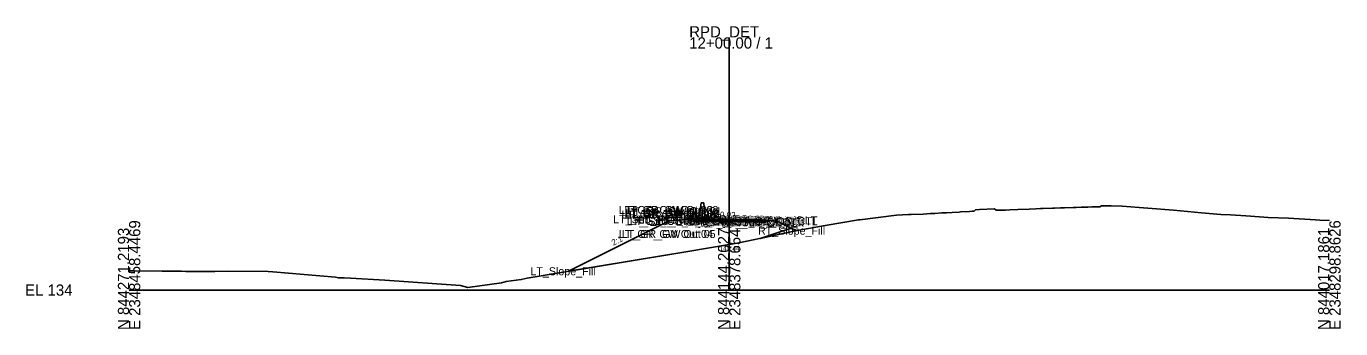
# Model space of a CAD drawing. Extents: x -26 to 2348503, y -10 to 844218.
# Drawn here: x -25.7 to 302.8, y 1990.3 to 2066.1 of the extents above; entities that cross this region are included whole.
import ezdxf

# ---------------------------------------------------------------- set-up
doc = ezdxf.new("R2010")
doc.units = 0
for name, color, linetype in [('Default', 7, 'Continuous'), ('Exist Cross Section Cell', 7, 'Continuous'), ('Exist XS Center Line Elevation Label', 7, 'Continuous'), ('Exist XS Ground Line', 7, 'Continuous'), ('Old_Level_1', 7, 'Continuous'), ('Prop CMT Pvmt Course 1', 7, 'Continuous'), ('Prop CMT Pvmt Course 2', 7, 'Continuous'), ('Prop CMT Pvmt Course 3', 7, 'Continuous'), ('Prop CMT Pvmt Surface', 7, 'Continuous'), ('Prop CMT Pvmt Surface Shoulder', 7, 'Continuous'), ('Prop CMT Shld Paved Course 1', 7, 'Continuous'), ('Prop CMT Shld Paved Course 2', 7, 'Continuous'), ('Prop CMT Shld Paved Course 3', 7, 'Continuous'), ('Prop CMT Slope Grass', 7, 'Continuous'), ('Prop CMT Subgrade Earthwork', 7, 'Continuous'), ('Prop XS Earthwork Shape', 7, 'Continuous'), ('Prop XS SE Text', 7, 'Continuous'), ('Scratch_Level_6', 7, 'Continuous'), ('Typical Median Barrier CELL', 7, 'Continuous')]:
    doc.layers.add(name, color=color, linetype=linetype)

# ---------------------------------------------------------------- blocks, each defined once
blk = doc.blocks.new('TYPE T DOUBLE FACE BARRIER')
at = {"layer": 'Typical Median Barrier CELL'}
for p, q in [((-0.33, 3.83), (-0.6, 1.3)), ((0, 3.83), (-0.33, 3.83)), ((0, 3.83), (0.33, 3.83)), ((0.33, 3.83), (0.6, 1.3)), ((-0.75, 0.91), (-1.21, 0.25)), ((-1.21, -0.17), (-1.21, 0.25)), ((0, 0), (0, 0)), ((0.75, 0.91), (1.21, 0.25)), ((1.21, -0.17), (1.21, 0.25)), ((-1.21, -0.17), (1.21, -0.17))]:
    blk.add_line(p, q, dxfattribs=at)
for centre, start, end in [((-1.43, 1.38), 325.0039, 353.9447), ((1.43, 1.38), 186.0553, 214.9937)]:
    blk.add_arc(centre, 0.833, start, end, dxfattribs=at)

msp = doc.modelspace()

# ---------------------------------------------------------------- linework, layer by layer
at = {"layer": 'Exist Cross Section Cell'}
for p, q in [((150, 2000), (150, 2063.28)), ((0, 2000), (150, 2000)), ((150, 2000), (300, 2000))]:
    msp.add_line(p, q, dxfattribs=at)
at = {"layer": 'Exist XS Ground Line'}
msp.add_lwpolyline([(0, 2004.81), (1.26, 2004.8), (8.23, 2004.75), (13.07, 2004.7), (14.18, 2004.69), (15.94, 2004.69), (21.43, 2004.68), (24.88, 2004.7), (34.74, 2004.63), (35.94, 2004.6), (51.57, 2003.2), (52.36, 2003.1), (53.72, 2003.04), (55.31, 2002.95), (63.93, 2002.5), (82.84, 2001.17), (84.64, 2000.68), (93.09, 2001.81), (94.25, 2002.13), (98.02, 2002.64), (99.49, 2003.01), (139.62, 2009.63), (150, 2011.44), (151.99, 2011.78), (154.79, 2012.29), (166.59, 2014.85), (173.96, 2016.13), (182.3, 2017.57), (182.66, 2017.61), (191.82, 2018.73), (193.28, 2018.8), (194.8, 2018.89), (195.48, 2018.91), (198.45, 2019.04), (200.27, 2019.14), (201.4, 2019.21), (203.14, 2019.31), (203.89, 2019.35), (204.35, 2019.37), (205.69, 2019.44), (207.5, 2019.54), (207.82, 2019.56), (210.06, 2019.68), (210.8, 2019.72), (211.2, 2019.72), (211.59, 2020.12), (212.58, 2020.17), (216.27, 2020.31), (216.7, 2019.97), (217.11, 2019.99), (217.57, 2020), (219.09, 2020.05), (220.17, 2020.1), (222.16, 2020.18), (224.97, 2020.3), (226.65, 2020.36), (227.8, 2020.39), (228.45, 2020.41), (230.83, 2020.5), (231.3, 2020.52), (232.83, 2020.58), (233.8, 2020.61), (236, 2020.69), (236.75, 2020.71), (237.97, 2020.75), (239.67, 2020.8), (240.67, 2020.83), (242.66, 2020.85), (243.09, 2021.09), (245.44, 2021.09), (248.18, 2021.01), (261.08, 2019.99), (268.04, 2019.36), (272.89, 2018.96), (275.29, 2018.81), (279.13, 2018.55), (282.55, 2018.32), (284.7, 2018.19), (289.8, 2018.01), (296.51, 2017.58), (297.64, 2017.5), (300, 2017.41)], dxfattribs=at)
at = {"layer": 'Prop CMT Pvmt Course 1'}
for p, q in [((150, 2017.71), (142, 2017.87)), ((142, 2017.87), (142, 2017.62)), ((142, 2017.62), (150, 2017.46)), ((150, 2017.46), (150, 2017.71)), ((150, 2017.71), (158, 2017.55)), ((150, 2017.46), (150, 2017.71)), ((150, 2017.46), (150, 2017.59)), ((150, 2017.59), (150, 2017.59)), ((150, 2017.59), (150, 2017.46)), ((150, 2017.46), (150, 2017.59)), ((150, 2017.59), (150, 2017.59)), ((150, 2017.59), (150, 2017.46)), ((150, 2017.46), (150, 2017.46)), ((158, 2017.3), (150, 2017.46)), ((150, 2017.46), (150, 2017.46)), ((158, 2017.55), (158, 2017.3))]:
    msp.add_line(p, q, dxfattribs=at)
at = {"layer": 'Prop CMT Pvmt Course 2'}
for p, q in [((142, 2017.62), (150, 2017.46)), ((150, 2017.46), (142, 2017.62)), ((142, 2017.62), (142, 2017.62)), ((150, 2017.46), (150, 2017.46)), ((158, 2017.3), (150, 2017.46)), ((150, 2017.46), (150, 2017.46)), ((150, 2017.46), (158, 2017.3)), ((158, 2017.3), (158, 2017.3))]:
    msp.add_line(p, q, dxfattribs=at)
at = {"layer": 'Prop CMT Pvmt Course 3'}
for p, q in [((150, 2017.46), (142, 2017.62)), ((142, 2017.62), (142, 2017.29)), ((142, 2017.29), (150, 2017.13)), ((150, 2017.13), (150, 2017.46)), ((150, 2017.46), (158, 2017.3)), ((150, 2017.13), (150, 2017.46)), ((158, 2017.3), (158, 2016.97)), ((158, 2016.97), (150, 2017.13))]:
    msp.add_line(p, q, dxfattribs=at)
at = {"layer": 'Prop CMT Pvmt Surface'}
for q in [(142, 2017.87), (158, 2017.55)]:
    msp.add_line((150, 2017.71), q, dxfattribs=at)
at = {"layer": 'Prop CMT Pvmt Surface Shoulder'}
for p, q in [((142, 2017.87), (142, 2017.87)), ((158, 2017.55), (158, 2017.55))]:
    msp.add_line(p, q, dxfattribs=at)
at = {"layer": 'Prop CMT Shld Paved Course 1'}
for p, q in [((142, 2017.87), (141.74, 2017.62)), ((141.74, 2017.62), (142, 2017.62)), ((142, 2017.87), (142, 2017.87)), ((142, 2017.62), (142, 2017.87)), ((158, 2017.55), (158, 2017.55)), ((158, 2017.55), (158.26, 2017.3)), ((158, 2017.3), (158, 2017.55)), ((158.26, 2017.3), (158, 2017.3))]:
    msp.add_line(p, q, dxfattribs=at)
at = {"layer": 'Prop CMT Shld Paved Course 2'}
for p, q in [((142, 2017.62), (141.74, 2017.62)), ((141.74, 2017.62), (141.74, 2017.62)), ((141.74, 2017.62), (142, 2017.62)), ((142, 2017.62), (142, 2017.62)), ((158, 2017.3), (158.26, 2017.3)), ((158.26, 2017.3), (158, 2017.3)), ((158, 2017.3), (158, 2017.3)), ((158.26, 2017.3), (158.26, 2017.3))]:
    msp.add_line(p, q, dxfattribs=at)
at = {"layer": 'Prop CMT Shld Paved Course 3'}
for p, q in [((141.24, 2017.61), (140.9, 2017.27)), ((140.9, 2017.27), (142, 2017.29)), ((141.74, 2017.62), (141.24, 2017.61)), ((142, 2017.62), (141.74, 2017.62)), ((142, 2017.29), (142, 2017.62)), ((158, 2017.3), (158.26, 2017.3)), ((158, 2016.97), (158, 2017.3)), ((158.26, 2017.3), (158.76, 2017.29)), ((158.76, 2017.29), (159.1, 2016.95)), ((159.1, 2016.95), (158, 2016.97))]:
    msp.add_line(p, q, dxfattribs=at)
at = {"layer": 'Prop CMT Slope Grass'}
for p, q in [((135, 2017.31), (109.79, 2004.71)), ((142, 2017.87), (135, 2017.31)), ((158, 2017.55), (162, 2017.23)), ((162, 2017.23), (166.72, 2014.87))]:
    msp.add_line(p, q, dxfattribs=at)
at = {"layer": 'Prop CMT Subgrade Earthwork'}
for p, q in [((140.9, 2017.27), (140.43, 2017.75)), ((142, 2017.29), (140.9, 2017.27)), ((150, 2017.13), (142, 2017.29)), ((159.1, 2016.95), (159.57, 2017.43)), ((150, 2017.13), (158, 2016.97)), ((158, 2016.97), (159.1, 2016.95))]:
    msp.add_line(p, q, dxfattribs=at)
at = {"layer": 'Prop XS Earthwork Shape'}
msp.add_lwpolyline([(162, 2017.23), (166.72, 2014.87), (166.59, 2014.85), (154.79, 2012.29), (151.99, 2011.78), (150, 2011.44), (139.62, 2009.63), (109.79, 2004.71), (135, 2017.31), (140.43, 2017.75), (140.9, 2017.27), (142, 2017.29), (150, 2017.13), (158, 2016.97), (159.1, 2016.95), (159.57, 2017.43)], close=True, dxfattribs=at)
at = {"layer": 'Scratch_Level_6'}
for p, q in [((165.45, 2015.51), (159.27, 2013.44)), ((166.66, 2014.9), (165.45, 2015.51)), ((166.72, 2014.87), (166.66, 2014.9)), ((159.27, 2013.44), (157.7, 2012.92))]:
    msp.add_line(p, q, dxfattribs=at)
msp.add_lwpolyline([(157.7, 2012.92), (166.59, 2014.85), (166.72, 2014.87)], dxfattribs=at)

# ---------------------------------------------------------------- block references
at = {"layer": 'Old_Level_1', "yscale": -0.9999999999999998, "rotation": 178.71900092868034}
msp.add_blockref('TYPE T DOUBLE FACE BARRIER', (143.21, 2018.01), dxfattribs=at)

# ---------------------------------------------------------------- texts
at = {"layer": 'Default'}
for s, height, p in [('LT_GR_GW Out 03', 2, (122.44, 2019.05)), ('LT_GR_GW Out 02', 2, (123.78, 2019.05)), ('LT_GR_GW Out 09', 2, (123.78, 2018.47)), ('LT_GR_GW Out 01', 2, (124.61, 2018.76)), ('LT_Sub_Trench_Out_DLT', 2, (120.99, 2016.75)), ('LT_GR_GW Out 06', 2, (123.06, 2017.89)), ('LT_GR_GW Out 07', 2, (123.78, 2017.89)), ('LT_GR_GW Out 08', 2, (124.05, 2018.18)), ('LT_GS_OS_CTL', 2, (124.37, 2016.31)), ('LT_Sub_Trench_Out', 2, (125.11, 2016.27)), ('LT_PS3_Shelf_Out', 2, (127.23, 2016.61)), ('LT_PS3_OEOP', 2, (131.98, 2016.62)), ('LT_PS2_OEOP', 2, (131.98, 2016.62)), ('LT_Sub_OEOT', 2, (132.08, 2016.29)), ('LT_PV3_OEOT', 2, (132.17, 2016.62)), ('LT_PV2_OEOT', 2, (132.17, 2016.62)), ('LT_PV1_OEOT', 2, (132.74, 2016.87)), ('LT_PS1_OEOP', 2, (132.8, 2016.87)), ('RT_Sub_OEEOP', 2, (139.17, 2016.13)), ('LT_Sub_OEEOP', 2, (139.21, 2016.13)), ('RT_PV2_OEEOP', 2, (139.26, 2016.46)), ('RT_PV3_OEEOP', 2, (139.26, 2016.46)), ('LT_PV2_OEEOP', 2, (139.31, 2016.46)), ('LT_PV3_OEEOP', 2, (139.31, 2016.46)), ('RT_PV1_OEEOP', 2, (139.83, 2016.59)), ('LT_PV1_OEEOP', 2, (139.87, 2016.59)), ('RT_PV2_IEEOP', 2, (139.91, 2016.46)), ('LT_PV2_IEEOP', 2, (139.95, 2016.46)), ('RT_Sub_Trench_Out_DLT', 2, (140.09, 2016.43)), ('RT_PV1_IEEOP', 2, (140.47, 2016.59)), ('LT_PV1_IEEOP', 2, (140.52, 2016.59)), ('RT_Sub_Trench_Out', 2, (143.25, 2015.95)), ('PV2_PGL', 2, (143.91, 2016.46)), ('PV1_PGL', 2, (144.47, 2016.71)), ('RT_PS3_Shelf_Out', 2, (144.69, 2016.29)), ('RT_Sub_OEOT', 2, (148.03, 2015.97)), ('RT_PV3_OEOT', 2, (148.13, 2016.3)), ('RT_PV2_OEOT', 2, (148.13, 2016.3)), ('RT_PS3_OEOP', 2, (148.44, 2016.3)), ('RT_PS2_OEOP', 2, (148.44, 2016.3)), ('RT_PV1_OEOT', 2, (148.69, 2016.55)), ('RT_PS1_OEOP', 2, (148.76, 2016.55)), ('RT_GS_OS_CTL', 2, (151.32, 2016.23)), ('LT_GR_GW Out 04', 2, (122.44, 2013.05)), ('LT_GR_GW Out 05', 2, (123.11, 2013.05)), ('RT_Slope_Fill', 2, (157.19, 2013.87)), ('LT_Slope_Fill', 2, (100.31, 2003.71)), ('-', 0.0001, (0, 2000))]:
    msp.add_text(s, height=height, dxfattribs=at).set_placement(p)
at = {"layer": 'Exist Cross Section Cell'}
for s, p in [('12+00.00 / 1', (140, 2060.48)), ('RPD_DET', (140, 2063.28)), ('EL 134', (-26, 1998.6))]:
    msp.add_text(s, height=2.8, dxfattribs=at).set_placement(p)
for s, p in [('E 2348458.4469', (2.8, 1990)), ('E 2348378.6547', (152.8, 1990)), ('E 2348298.8626', (302.8, 1990)), ('N 844271.2193', (0, 1990)), ('N 844144.2027', (150, 1990)), ('N 844017.1861', (300, 1990))]:
    msp.add_text(s, height=2.8, rotation=90, dxfattribs=at).set_placement(p)
at = {"layer": 'Exist XS Center Line Elevation Label'}
msp.add_text('145.44', height=1.2, dxfattribs=at).set_placement((147.55, 2009.84))
at = {"layer": 'Prop XS SE Text'}
for s, rotation, p in [('0.02', 358.8542, (147.68, 2018.13)), ('2:1', 333.4349, (163.4, 2016.93)), ('2:1', 26.5651, (121.06, 2011.09))]:
    msp.add_text(s, height=1.5, rotation=rotation, dxfattribs=at).set_placement(p)

doc.saveas('drawing.dxf')
